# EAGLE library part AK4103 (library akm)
Digital Audio Transmitter (DIT) Single Output, 24-Bit, 192 kHz
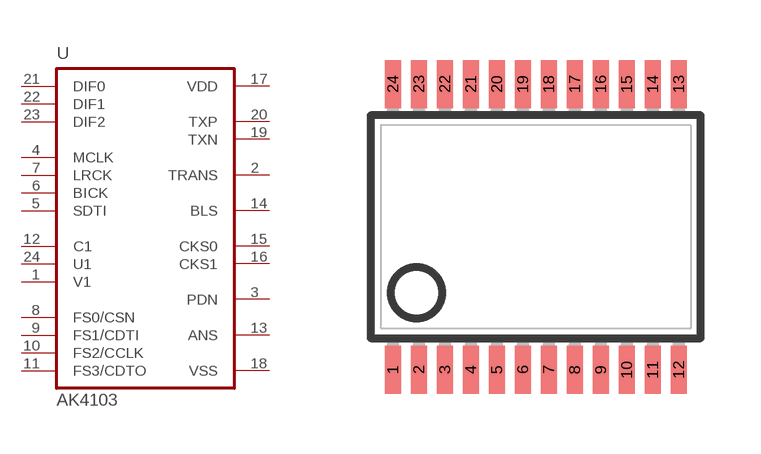
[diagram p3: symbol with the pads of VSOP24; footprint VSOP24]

Designator prefix U

## AK4103A  [VSOP24]
1  V1  in
2  TRANS  in
3  PDN  in
4  MCLK  in
5  SDTI  in
6  BICK
7  LRCK
8  FS0/CSN
9  FS1/CDTI
10  FS2/CCLK
11  FS3/CDTO
12  C1  in
13  ANS
14  BLS
15  CKS0  in
16  CKS1  in
17  VDD
18  VSS
19  TXN  out
20  TXP  out
21  DIF0  in
22  DIF1  in
23  DIF2  in
24  U1  in

## Footprint VSOP24 (pad centres in mm)
VSOP24 7.8 x 5.6 mm, pitch .65 mm
smd 0.4 x 1.2: 1 -3.575,-3.57; 2 -2.925,-3.57; 3 -2.275,-3.57; 4 -1.625,-3.57; 5 -0.975,-3.57; 6 -0.325,-3.57; 7 0.325,-3.57; 8 0.975,-3.57; 9 1.625,-3.57; 10 2.275,-3.57; 11 2.925,-3.57; 12 3.575,-3.57; 13 3.575,3.57; 14 2.925,3.57; 15 2.275,3.57; 16 1.625,3.57; 17 0.975,3.57; 18 0.325,3.57; 19 -0.325,3.57; 20 -0.975,3.57; 21 -1.625,3.57; 22 -2.275,3.57; 23 -2.925,3.57; 24 -3.575,3.57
